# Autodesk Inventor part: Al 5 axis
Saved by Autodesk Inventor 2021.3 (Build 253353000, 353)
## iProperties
Created: 2024-03
Part Number: Al 5 axis
Material: Generic
Document SubType Name: Modeling
Designer: AdminForWorker
Density: 1 g/cm^3
Appearance: Default
Title: Al 5 axis
Author: AdminForWorker
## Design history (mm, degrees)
feature "Al"
body "Solid1"
